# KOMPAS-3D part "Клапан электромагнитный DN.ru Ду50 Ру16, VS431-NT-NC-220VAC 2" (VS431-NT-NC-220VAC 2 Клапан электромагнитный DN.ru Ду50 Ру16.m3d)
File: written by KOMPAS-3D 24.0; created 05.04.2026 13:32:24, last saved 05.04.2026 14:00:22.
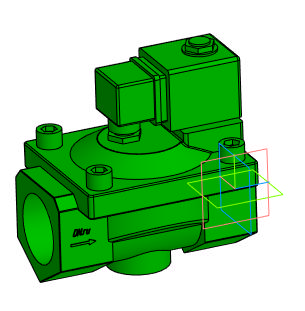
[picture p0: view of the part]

Document properties: Автор: artio; Полное имя файла: C:\Users\artio\OneDrive\Рабочий стол\Клапан электромагнитный DN.ru\VS431\VS431-NT-NC\VS431-NT-NC-220VAC\Ду50\VS431-NT-NC-220VAC 2 Клапан электромагнитный DN.ru Ду50 Ру16.m3d

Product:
- Body: Тело 1  | qty 1
    Масса: 6.703651
- Part/product: Клапан электромагнитный DN.ru Ду50 Ру16  | designation VS431-NT-NC-220VAC 2
    Масса: 3.341
    Раздел спецификации: Прочие изделия
    Примечание: D130-04673
    additional columns: ef56311e-7521-43dc-8291-0e6108b3d81d; artio; c; Шероховатость не задана; Да

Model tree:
1. Операция без истории:1

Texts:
  VS431-NT-NC-220VAC 2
